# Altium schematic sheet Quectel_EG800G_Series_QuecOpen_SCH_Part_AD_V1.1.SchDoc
size A2; Organization: Altium Limited; Address1: L3, 12a Rodborough Rd; Address2: Frenchs Forest; Address3: NSW; Address4: Australia 2086
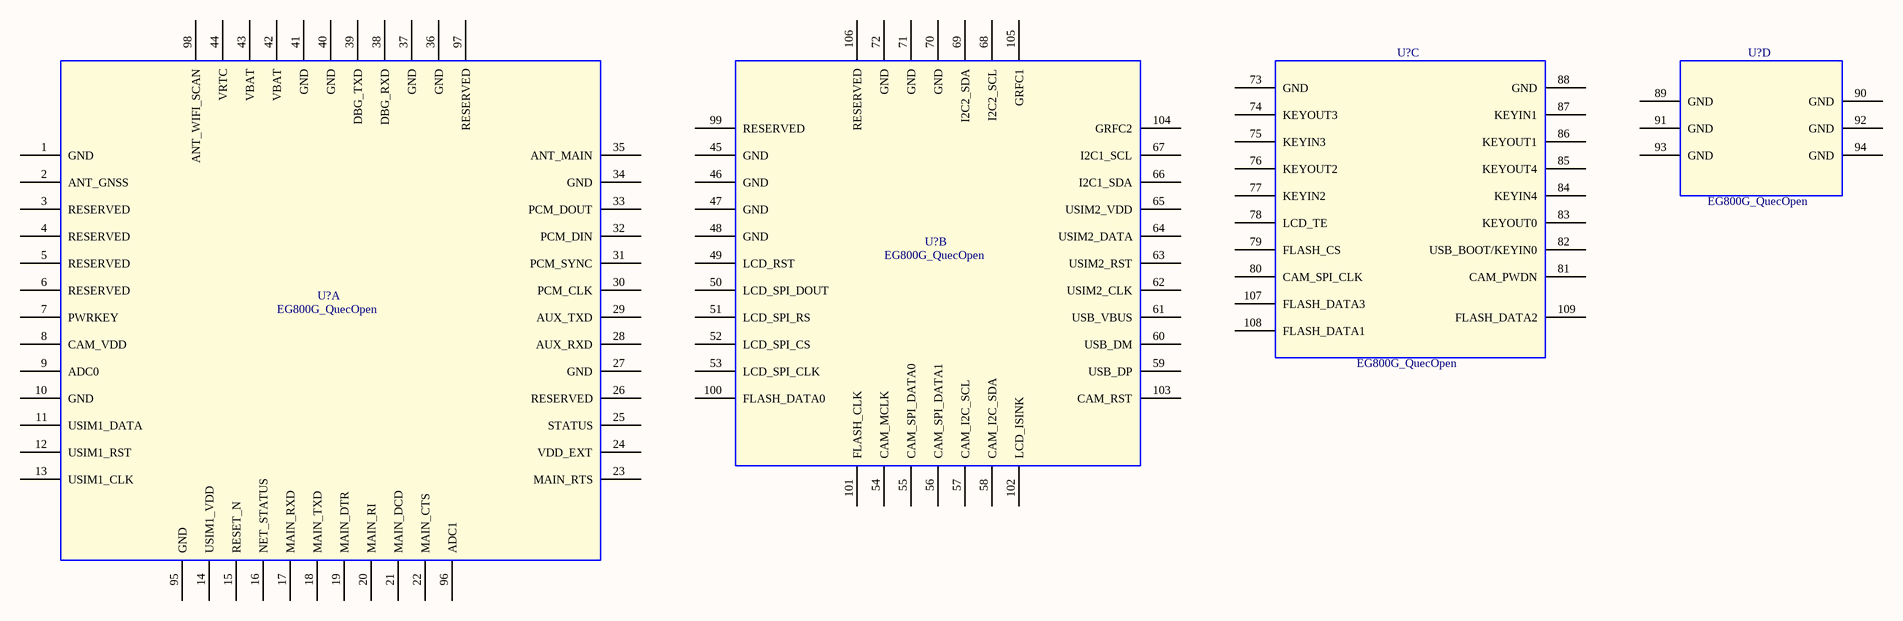
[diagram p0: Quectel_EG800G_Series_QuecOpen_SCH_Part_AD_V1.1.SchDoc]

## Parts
(Parts that share a designator on the sheet are numbered #1, #2 ... from top to bottom, then left to right.)
U?#1  EG800G_QuecOpen  [EG800G_QuecOpen]  (part D of 4)
U?#2  EG800G_QuecOpen  [EG800G_QuecOpen]  (part C of 4)
U?#3  EG800G_QuecOpen  [EG800G_QuecOpen]  (part B of 4)
U?#4  EG800G_QuecOpen  [EG800G_QuecOpen]  (part A of 4)

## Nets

Not connected (* = marked no-connect by the designer): U?#1 89(GND) 90(GND) 91(GND) 92(GND) 93(GND) 94(GND); U?#2 73(GND) 74(KEYOUT3) 75(KEYIN3) 76(KEYOUT2) 77(KEYIN2) 78(LCD_TE) 79(FLASH_CS) 80(CAM_SPI_CLK) 81(CAM_PWDN) 82(USB_BOOT/KEYIN0) 83(KEYOUT0) 84(KEYIN4) 85(KEYOUT4) 86(KEYOUT1) 87(KEYIN1) 88(GND) 107(FLASH_DATA3) 108(FLASH_DATA1) 109(FLASH_DATA2); U?#3 45(GND) 46(GND) 47(GND) 48(GND) 49(LCD_RST) 50(LCD_SPI_DOUT) 51(LCD_SPI_RS) 52(LCD_SPI_CS) 53(LCD_SPI_CLK) 54(CAM_MCLK) 55(CAM_SPI_DATA0) 56(CAM_SPI_DATA1) 57(CAM_I2C_SCL) 58(CAM_I2C_SDA) 59(USB_DP) 60(USB_DM) 61(USB_VBUS) 62(USIM2_CLK) 63(USIM2_RST) 64(USIM2_DATA) 65(USIM2_VDD) 66(I2C1_SDA) 67(I2C1_SCL) 68(I2C2_SCL) 69(I2C2_SDA) 70(GND) 71(GND) 72(GND) 99(RESERVED) 100(FLASH_DATA0) 101(FLASH_CLK) 102(LCD_ISINK) 103(CAM_RST) 104(GRFC2) 105(GRFC1) 106(RESERVED); U?#4 1(GND) 2(ANT_GNSS) 3(RESERVED) 4(RESERVED) 5(RESERVED) 6(RESERVED) 7(PWRKEY) 8(CAM_VDD) 9(ADC0) 10(GND) 11(USIM1_DATA) 12(USIM1_RST) 13(USIM1_CLK) 14(USIM1_VDD) 15(RESET_N) 16(NET_STATUS) 17(MAIN_RXD) 18(MAIN_TXD) 19(MAIN_DTR) 20(MAIN_RI) 21(MAIN_DCD) 22(MAIN_CTS) 23(MAIN_RTS) 24(VDD_EXT) 25(STATUS) 26(RESERVED) 27(GND) 28(AUX_RXD) 29(AUX_TXD) 30(PCM_CLK) 31(PCM_SYNC) 32(PCM_DIN) 33(PCM_DOUT) 34(GND) 35(ANT_MAIN) 36(GND) 37(GND) 38(DBG_RXD) 39(DBG_TXD) 40(GND) 41(GND) 42(VBAT) 43(VBAT) 44(VRTC) 95(GND) 96(ADC1) 97(RESERVED) 98(ANT_WIFI_SCAN)

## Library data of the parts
U?#1-U?#4 = EG800G_QuecOpen: EG800G_QuecOpen Module 109LGA 15.8x17.7mm H2.6mm RO; Manufacturer: QUECTEL; Geometry.Height: 2.6mm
